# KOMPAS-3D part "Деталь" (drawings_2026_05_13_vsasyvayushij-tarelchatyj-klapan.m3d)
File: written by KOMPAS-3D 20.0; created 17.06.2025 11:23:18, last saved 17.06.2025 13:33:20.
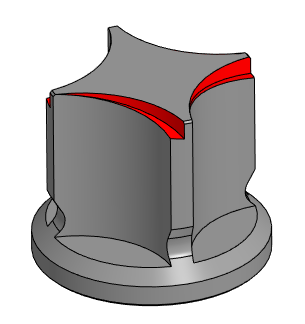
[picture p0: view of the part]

Document properties: Автор: VLAD; Полное имя файла: C:\Users\VLAD\Desktop\Всасывающий тарельчатый клапан.m3d

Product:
- Part/product: Деталь
    Масса: 0.388352

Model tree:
1. Эскиз:1
2. Элемент вращения:1
     Угол 1 = 360
3. Эскиз:2  (with: Элемент вращения:1)
4. Элемент выдавливания:1
     Расстояние 2 = 36.35
5. Массив по концентрической сетке:1  (with: Элемент выдавливания:1, Элемент вращения:1)  (4 pattern instances)
     Шаг 2 = 360
6. Эскиз:12  (with: Элемент вращения:1)
7. Спираль:2
     Число витков = 1; Шаг = 21; Высота = 21; Диаметр 1 = 52.54; Диаметр 2 = 10; Угол = 191.2
8. Перпендикулярная плоскость:4
9. Эскиз:14
10. Элемент по траектории:8
11. Массив по концентрической сетке:2  (with: Элемент по траектории:8, Спираль:2, Элемент вращения:1)  (4 pattern instances)
     Шаг 2 = 360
